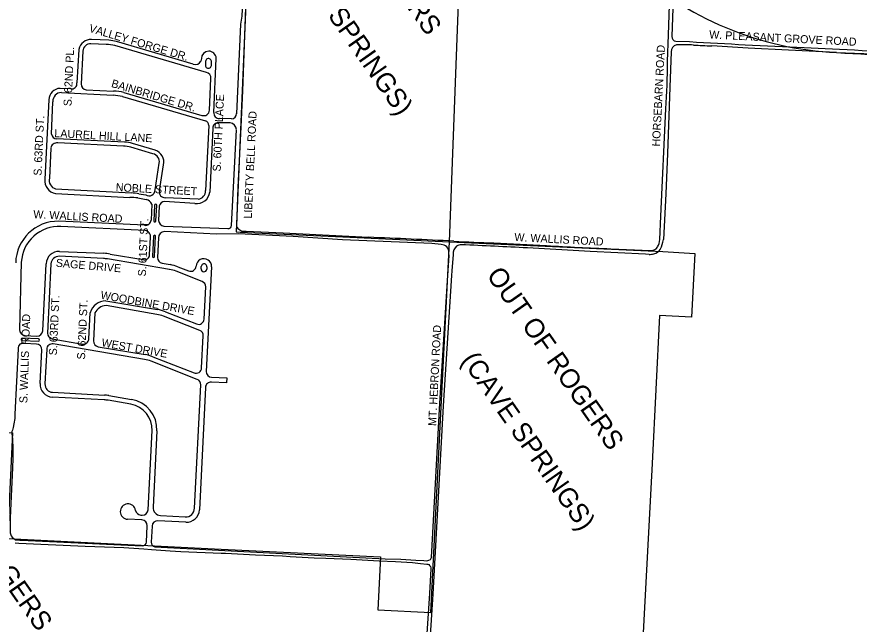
# Model space of a CAD drawing. Extents: x 0 to 712119, y 0 to 761125.
# Drawn here: x 662915 to 668176, y 714980 to 718772 of the extents above; entities that cross this region are included whole.
import ezdxf

# ---------------------------------------------------------------- set-up
doc = ezdxf.new("R2010")
doc.units = 0
for name, color, linetype in [('ISLANDS', 7, 'Continuous'), ('PAVED ROADS', 7, 'Continuous'), ('Priority 11', 7, 'Continuous'), ('street names', 7, 'Continuous')]:
    doc.layers.add(name, color=color, linetype=linetype)

msp = doc.modelspace()

# ---------------------------------------------------------------- linework, layer by layer
at = {"layer": 'ISLANDS'}
msp.add_lwpolyline([(664310.7, 717427.5), (664952, 717398.1), (665618, 717367.5), (665668.3, 718692.6), (665718.7, 720018.1), (664396.1, 720078.2), (664341, 718753), (664286, 717428.7)], close=True, dxfattribs=at)
msp.add_lwpolyline([(661495, 714923.1), (661558.5, 716237.1), (662888.7, 716173.6), (662856, 715514.6), (664191, 715448.9), (665185.7, 715399.9), (665169.4, 715068.9), (665500.5, 715052.6), (665517.3, 715383.6), (665517.3, 715383.6), (665550.9, 716046.6), (665618, 717367.5), (666949.9, 717306.3), (667149.6, 717295.4), (667129.4, 716895.9), (666929.7, 716906.8), (666883, 715983.1), (666813.6, 714653)], dxfattribs=at)
at = {"layer": 'PAVED ROADS'}
for points in [[(664348.9, 719553.2), (664330.1, 719144.4), (664334.3, 719088.5), (664319.5, 718776.1), (664312.8, 718725.5), (664287.5, 718167.6)], [(666979.9, 718493.1), (666985.1, 718659.1), (666999.1, 719096.3)], [(664346.9, 718946.4), (664323.7, 718310.1), (664314.2, 718086.4), (664296.1, 717706.8), (664287.6, 717465.3)], [(667016, 718946.1), (667006.1, 718650.1)], [(663489.8, 718625.9), (663381.7, 718630.8)], [(664016.6, 718476.6), (663537.4, 718617.4)], [(667032.1, 718620.5), (667117.3, 718617.5)], [(663302.4, 718569.1), (663290.7, 718359.9)], [(663327, 718558.4), (663316.7, 718353.8)], [(663473.2, 718600.4), (663378, 718604.4)], [(663473.2, 718600.4), (663473.2, 718600.4)], [(664098.9, 718424.8), (663527.7, 718593.1)], [(668035.7, 718549.2), (667734.6, 718563.3), (667484, 718576.1), (667255.1, 718590.4)], [(667465.1, 718598.3), (667743.8, 718585.4), (668053.1, 718570.2)], [(664067.8, 718511.5), (664064.8, 718495.9)], [(664144.8, 718175.9), (664160.4, 718512.5)], [(667002.6, 718553.5), (666994.6, 718332.4), (666979.7, 717918.7), (666967.7, 717666.3), (666953.6, 717382.1)], [(664094, 718493.6), (664093.1, 718469.7)], [(664130.2, 718469.4), (664131.1, 718490.6)], [(664117.6, 718188.7), (664127.5, 718386.9)], [(663251.4, 718322.4), (663186.1, 718325.6)], [(663193.2, 718298.8), (663517.6, 718282.7)], [(663348.9, 718317), (663519.8, 718309)], [(663583.9, 718300.3), (664071.1, 718157.1)], [(663115.1, 718253.5), (663090.4, 717757.8)], [(663131.5, 718039.2), (663140.5, 718242.5)], [(663575.2, 718274.5), (664093.5, 718123.3)], [(666930.4, 717382.6), (666937.3, 717527.6), (666968, 718198.8)], [(664256.2, 718134.4), (664180.3, 718137.4)], [(664113.3, 718094.7), (664094.2, 717687.1)], [(664247.5, 718109.7), (664174.2, 718111.4)], [(664139.3, 718076.1), (664120.2, 717678.4)], [(664254.9, 717469.2), (664286.4, 718067.7)], [(663587.2, 717989.7), (663164.2, 718011.4)], [(663580.4, 717964.7), (663170.4, 717984.7)], [(663779.2, 717940.3), (663636.8, 717982.1)], [(663126.8, 717953.2), (663118.5, 717764.9)], [(663765.5, 717917.3), (663627.2, 717958.6)], [(663779.5, 717691.1), (663804.7, 717858.5)], [(663806.2, 717685.8), (663830.9, 717847.1)], [(663156.5, 717668.5), (663620, 717644.7)], [(663157.5, 717697.6), (663630.5, 717672.7)], [(663677.3, 717667.9), (663721, 717660.3)], [(663670.2, 717641.8), (663723, 717630.8)], [(664027.5, 717607), (663837.7, 717618.2)], [(664047.2, 717633.8), (663842.4, 717643)], [(663757.7, 717602.9), (663753.8, 717503.4)], [(663774.8, 717595.3), (663769.9, 717499.4)], [(663783.8, 717498.7), (663788.8, 717594.5)], [(663804.7, 717589.9), (663800.7, 717499.9)], [(663712.3, 717470.4), (663176.4, 717496.2)], [(663716.9, 717437.2), (663190.3, 717462.5)], [(663832.3, 717465.9), (664234, 717451.2)], [(663768, 717401.6), (663761.8, 717277.4)], [(663768, 717401.6), (663768, 717401.6)], [(663775.8, 717276.7), (663782, 717400.9)], [(665507.8, 717356), (664949.4, 717380.4), (664641.8, 717400.8), (664298.3, 717416.3), (664162.5, 717414.5), (663836.8, 717431)], [(664336.1, 717433.9), (664347.4, 717433.9), (664577.9, 717423.6), (665111.9, 717395.5)], [(663743.9, 717287.7), (663749.7, 717395.1)], [(663799.6, 717392.4), (663793.5, 717269.7)], [(665893.9, 717360.5), (666223, 717343.7)], [(663181.9, 717306.8), (663457.9, 717295.6)], [(666863.8, 717289.1), (666842.6, 717290.2), (666495.8, 717306.5), (666104.3, 717328.9)], [(666624.6, 717324.2), (666870.6, 717312.5)], [(663457.4, 717263), (663180.4, 717276.8)], [(663457.4, 717263), (663457.4, 717263)], [(663867.6, 717195.4), (663481.8, 717260.3)], [(663497.4, 717290), (663703.7, 717256.3)], [(663775.8, 717276.7), (663775.8, 717276.7)], [(665216.5, 715387.6), (665313.6, 715386.3), (665407.3, 715379.9), (665457.6, 715376.7), (665475.4, 715375.7), (665489.1, 715379.1), (665498, 715384.3), (665502.9, 715392.1), (665505, 715396), (665558, 716360), (665606.9, 717156.3), (665609.3, 717188.1), (665614.7, 717282.6)], [(665639.7, 717287.7), (665632.1, 717187.1), (665630.1, 717156.3), (665577.7, 716344.1), (665513.8, 715166.3), (665497.6, 714909.4), (665488.4, 714777.2), (665477, 714642.8), (665467.3, 714536.9), (665459, 714421.3), (665443.7, 714234.9), (665439.6, 714144.1), (665441.3, 714079.1), (665442.9, 714012.9), (665443.8, 713890.4), (665441.1, 713784.1), (665434.9, 713591.6), (665431.9, 713498.7), (665428.2, 713427.2), (665434.2, 713414.3)], [(662943, 717240.1), (662932.6, 716819.6)], [(663077.2, 716812.4), (663098, 717230.8)], [(663128, 717229.3), (663106.4, 716797.1)], [(663822.6, 717233.4), (663872.6, 717225)], [(663920.5, 717211.7), (663987.3, 717185.5)], [(664066, 717199.1), (664066.7, 717212.8)], [(664130.9, 717211), (664098.4, 716558.5)], [(664102.7, 717210.9), (664102, 717197.2)], [(664072.5, 717119.7), (663909.6, 717183.8)], [(664084.7, 716885.2), (664094.6, 717085.4)], [(663470.6, 716998.5), (663794.6, 716944.1)], [(663789.6, 716914.5), (663472.5, 716968.7)], [(663842.6, 716930.7), (664036.9, 716854.4)], [(663365, 716761.9), (663373.1, 716924.4)], [(663403.1, 716922.9), (663394.4, 716748.7)], [(664057.3, 716814.1), (663831.6, 716902.8)], [(662965.8, 716782.9), (663040.5, 716779.2)], [(664069.4, 716579.6), (664079.4, 716779.8)], [(662941.7, 716759.5), (662941.6, 716758.5)], [(662947.8, 716751.7), (663049.4, 716746.7)], [(663050.1, 716760.7), (662948.5, 716765.7)], [(663038, 716729.2), (662964.6, 716732.9)], [(663056.2, 716752.8), (663056.2, 716753.8)], [(663135.6, 716760.9), (663324.2, 716729.1)], [(663711.7, 716633.5), (663142.2, 716729.3)], [(662922.6, 716699.4), (662903, 716290.5), (662901.7, 716264.8), (662897.2, 716230.5), (662891.3, 716207.5), (662888.1, 716190.8), (662884.5, 716183.2), (662884.5, 716169.7), (662887.2, 716134.9), (662889, 716116.9), (662890.8, 716094.8), (662890.7, 716014.8), (662888.5, 715956.5), (662873.9, 715643.5), (662872.6, 715575.4), (662873.9, 715549.5), (662880.1, 715531.2), (662886.8, 715522.2), (662906.1, 715507.1), (662933.3, 715503.5), (662943, 715503.5), (663698.8, 715469)], [(663060.7, 716481.6), (663071.2, 716692.5)], [(663101.4, 716696.6), (663090.6, 716480.1)], [(663423.5, 716712.4), (663716.6, 716663.1)], [(664042, 716508.5), (663753.7, 716621.9)], [(663764.6, 716649.8), (664021.7, 716548.7)], [(664131.6, 716521.8), (664226.5, 716517.1), (664225, 716487.1), (664130.1, 716491.8)], [(664024.8, 715704), (664064.2, 716474.2)], [(664093.4, 716458.6), (664055.3, 715692.8)], [(663137.9, 716427.7), (663462.6, 716410.2)], [(663489.5, 716407.2), (663631.3, 716383.4)], [(663461, 716380.3), (663136.3, 716397.7)], [(663626.3, 716353.8), (663484.5, 716377.7)], [(663734.9, 715693.7), (663759.6, 716188.1)], [(663789.5, 716186.6), (663766.9, 715709.9)], [(663789.5, 716186.6), (663789.5, 716186.6)], [(663696.7, 715630.6), (663607, 715635)], [(663689.6, 715660.9), (663698.2, 715660.5)], [(663971.4, 715616.9), (663796.6, 715625.6)], [(663811.7, 715657.7), (663967.2, 715649.7)], [(663724.9, 715492.8), (663730, 715593.9)], [(663759.9, 715592.4), (663754.9, 715491.3), (663754.9, 715491.3)], [(662904.8, 715487.7), (662927.6, 715486.2), (663342.7, 715465.8), (663583.5, 715458.6), (663708.1, 715449.3), (663756.3, 715446.2), (663873, 715438.5), (663940.1, 715434.3), (664191.8, 715423.2), (664218.9, 715423.6), (664406.6, 715413.7), (664573.7, 715405.7), (664622.5, 715402), (664696.5, 715399), (664771.5, 715394), (664845.5, 715391), (665001, 715385), (665178.5, 715376), (665280, 715371), (665386.5, 715364.5), (665436.5, 715359), (665476.5, 715354.5), (665483, 715353.5), (665488.5, 715351.5), (665493, 715347), (665498, 715340), (665501, 715332.5), (665501, 715324.5), (665492.6, 715172), (665480, 714983.6), (665466.1, 714767.4)], [(663777.6, 715463.4), (664572.7, 715421.4), (665216.5, 715387.6)]]:
    msp.add_lwpolyline(points, dxfattribs=at)
msp.add_lwpolyline([(664310.4, 718727.8), (664310.4, 718727.8), (664310.4, 718727.8), (664310.4, 718727.8), (664310.4, 718727.8)], close=True, dxfattribs=at)
for centre, radius, start, end in [((663378.6, 718552.9), 78, 87.7687, 168.0083), ((663478.3, 718423.2), 203, 73.0725, 86.7674), ((667034.2, 718648.6), 28.2, 176.9204, 265.8031), ((669070.9, 750887.8), 32329.4, 266.53573, 267.15305), ((663377, 718554.1), 50.3, 88.8752, 175.0808), ((663461.7, 718308.6), 292, 76.9346, 87.7527), ((664114.1, 718511.5), 46.3, 1.2247, 180.1138), ((667045.1, 718555.2), 42.5, 103.9054, 182.2865), ((667082.2, 717694.2), 903.6, 86.2496, 93.0001), ((668040.7, 736476), 17902.8, 267.12026, 267.48483), ((673192.1, 815630), 97195.7, 266.969225, 267.41493), ((664112.7, 718493.2), 18.6, 352.0387, 178.8148), ((664170.4, 718512), 10, 177.0447, 177.0452), ((671419.7, 781551.1), 63092.8, 266.925456, 267.292135), ((664030.8, 718510.9), 37.1, 247.4444, 336.2536), ((664111.6, 718469.4), 18.5, 179.2582, 359.9103), ((662054.3, 718544.6), 4925.9, 355.9747, 359.4009), ((664091.8, 718389.8), 35.8, 355.5002, 78.6309), ((663256.7, 718356.3), 34.2, 261.1814, 5.9996), ((663352.7, 718352.7), 36, 178.3182, 263.921), ((663187.8, 718252.8), 72.8, 91.3587, 179.4564), ((663191.7, 718247.4), 51.4, 88.2835, 185.5466), ((663507.7, 717979.1), 330.1, 76.6548, 87.9001), ((663503.6, 717975.6), 307.4, 76.525, 87.3759), ((664083, 718189.5), 34.5, 249.7218, 358.6098), ((664179.9, 718172.6), 35.2, 174.6804, 270.6987), ((664253.2, 718168.6), 34.3, 275.0079, 358.3682), ((664084.6, 718096), 28.7, 357.4762, 72.0976), ((664172.4, 718078.2), 33.2, 86.904, 183.6577), ((664244.5, 718067.9), 41.9, 359.815, 85.8333), ((663164.9, 718045.3), 34, 190.4215, 268.7361), ((663164, 717947.7), 37.6, 80.1103, 171.5252), ((663580.6, 717780.9), 208.9, 74.397, 88.179), ((663582.1, 717796.5), 168.3, 74.4229, 90.5652), ((663753.7, 717865.2), 79.3, 346.8098, 71.265), ((663753.1, 717866.6), 52.2, 351.0431, 76.3108), ((663171.7, 717748.9), 81.8, 173.7648, 259.2622), ((663173, 717751.5), 56.1, 166.1671, 253.9545), ((663605.5, 717197.9), 475.5, 81.3082, 86.9849), ((663741.4, 717692.4), 38.1, 237.5244, 358.069), ((663839.6, 717677.4), 34.5, 165.7821, 274.7152), ((664039.2, 717687.8), 81.6, 261.7576, 353.3974), ((664041.6, 717686.2), 52.6, 276.177, 1.001), ((663570.9, 716364.6), 1281, 85.5533, 87.8035), ((663719.4, 717590.8), 40.1, 17.5808, 84.8633), ((663837.9, 717584.6), 33.6, 90.2939, 170.884), ((663781.8, 717594.9), 7, 357.0451, 177.0451), ((663173.7, 717230.2), 266, 89.4116, 178.7163), ((663177.1, 717228.5), 234.4, 86.7864, 177.1706), ((663718.3, 717505.4), 35.6, 260.3321, 356.7444), ((663776.9, 717499), 7, 177.0452, 357.0469), ((663835.4, 717500.5), 34.7, 180.8906, 264.7587), ((664239.2, 717466.2), 15.9, 250.7446, 10.7791), ((664320.5, 717473.5), 33.9, 194.0491, 247.9144), ((663713.3, 717400.6), 36.8, 351.4395, 84.344), ((663775, 717401.2), 7, 357.1454, 177.1504), ((663840.3, 717390.4), 40.8, 94.9639, 177.1808), ((664329, 717462.3), 29.3, 223.5293, 284.0258), ((662583.5, 655225.7), 62221.3, 87.180151, 87.671174), ((665481.7, 716801.2), 555.4, 79.4629, 87.3094), ((666170.6, 726368.6), 9012.4, 266.65347, 268.24026), ((665688.1, 717306), 43.1, 84.3274, 127.3908), ((664017.7, 678579.6), 38805.4, 86.9176, 87.52655), ((666847.7, 717381.7), 82.7, 325.6275, 0.6179), ((666779.6, 717403.8), 175.4, 331.5989, 352.875), ((663177.9, 717226.9), 80, 87.1479, 177.1479), ((663447.8, 717081.4), 214.4, 76.6081, 87.3009), ((665564.6, 717300.5), 50.3, 20.6124, 68.2062), ((665126, 717259.1), 489.2, 2.7524, 6.9397), ((665705.6, 717290.8), 66, 131.461, 182.6842), ((667203, 733340.7), 16026.9, 266.49441, 267.93182), ((666876.8, 717356.9), 44.9, 262.0681, 330.7807), ((666883.3, 717349.9), 58.5, 280.0288, 329.7331), ((663177.9, 717226.9), 50, 87.1479, 177.1479), ((663447, 717053.3), 210, 80.448, 87.1479), ((663711.9, 717287.2), 32, 255.0219, 0.9167), ((663768.8, 717277), 7, 177.1479, 357.1479), ((663775.8, 717276.7), 0.000000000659, 45, 135), ((663828.4, 717267.9), 35, 177.1479, 260.448), ((664083, 717213.5), 48, 357.0446, 177.0451), ((666870.8, 717364.5), 75.7, 264.6839, 287.4347), ((663832.7, 716988.3), 210, 68.5387, 80.448), ((663832.7, 716988.3), 240, 68.5387, 80.448), ((664000.1, 717218), 35, 248.5404, 356.602), ((664084, 717198.2), 18, 177.0463, 356.8888), ((664084.7, 717211.8), 18, 357.0446, 177.0451), ((664059.7, 717087.2), 35, 357.1479, 68.5387), ((663471.5, 716896.1), 102.4, 90.5056, 163.9539), ((663475.1, 716889.3), 79.5, 91.8922, 154.9766), ((663754.8, 716707.4), 240, 68.5387, 80.448), ((663754.8, 716707.4), 210, 68.5387, 80.448), ((664049.7, 716886.9), 35, 248.5387, 357.1479), ((662967.6, 716817.8), 35, 177.1985, 267.129), ((663042.2, 716814.1), 35, 267.1479, 357.1479), ((663141.4, 716795.4), 35, 177.1479, 260.448), ((664044.4, 716781.5), 35, 357.1479, 68.5387), ((662955.1, 716701.7), 32.6, 73.1215, 183.9092), ((662948.1, 716758.2), 6.5, 177.1479, 267.1479), ((662948.2, 716759.2), 6.5, 87.1479, 177.1479), ((663036.2, 716694.3), 35, 357.1479, 87.1479), ((663049.7, 716753.2), 6.5, 267.1479, 357.1479), ((663049.7, 716754.2), 6.5, 357.1479, 87.1479), ((663136.4, 716694.8), 35, 80.448, 177.1479), ((663330, 716763.6), 35, 260.448, 357.1479), ((663429.3, 716746.9), 35, 177.1479, 260.448), ((663676.8, 716426.4), 210, 68.5387, 80.448), ((663676.8, 716426.4), 240, 68.5387, 80.448), ((664034.5, 716581.3), 35, 248.5387, 357.1479), ((664029.2, 716475.9), 35, 357.1479, 68.5387), ((664133.4, 716556.8), 35, 177.1481, 267.1481), ((663140.6, 716477.6), 80, 177.1479, 266.9233), ((663140.6, 716477.6), 50, 177.1479, 266.9233), ((664128.4, 716456.9), 35, 87.1479, 177.1481), ((663449.7, 716170.6), 240, 80.448, 86.9233), ((663449.7, 716170.6), 210, 80.448, 86.9233), ((663599.8, 716196), 160, 357.1479, 80.448), ((663599.8, 716196), 190, 357.1479, 80.448), ((663609.4, 715683), 48, 8.9668, 267.1479), ((663691.4, 715695.9), 35, 188.9668, 267.1479), ((663700, 715695.5), 35, 267.1479, 357.1479), ((663815.9, 715706.6), 49.1, 176.1311, 265.042), ((663970.5, 715703.9), 54.3, 266.5665, 0.0833), ((663975.4, 715696.8), 80, 267.1479, 357.1479), ((663695, 715595.6), 35, 357.1479, 87.1479), ((663794.9, 715590.6), 35, 87.1479, 177.1479), ((663700, 715494), 25, 267.3913, 357.1479), ((663783.5, 715491.4), 28.6, 180.0873, 258.2086)]:
    msp.add_arc(centre, radius, start, end, dxfattribs=at)
at = {"layer": 'Priority 11'}
msp.add_lwpolyline([(668035.7, 718549.2), (669564.9, 718492.9), (670028.3, 718562.8), (670397.3, 718550), (670799.9, 718421.5), (671357.4, 718377.7), (671357.4, 718377.7), (671803.7, 718259.9), (672268.1, 718018.9)], dxfattribs=at)
msp.add_arc((668129.8, 720581.9), 2034.9, 227.173, 267.3497, dxfattribs=at)

# ---------------------------------------------------------------- texts
at = {"layer": 'ISLANDS'}
for s, p in [('OUT OF ROGERS', (664705.7, 719750.4)), ('(CAVE SPRINGS)', (664547.3, 719219.5)), ('OUT OF ROGERS', (665845.1, 717158.3)), ('(CAVE SPRINGS)', (665686.7, 716627.3)), ('OUT OF ROGERS', (662275.1, 716029.7))]:
    msp.add_text(s, height=120, rotation=305, dxfattribs=at).set_placement(p)
at = {"layer": 'street names'}
for s, rotation, p in [('VALLEY FORGE DR.', 343.4102, (663361.9, 718680)), ('W. PLEASANT GROVE ROAD', 357.1138, (667238.5, 718637.7)), ('S. 62ND PL.', 87.3557, (663256.1, 718213.4)), ('HORSEBARN ROAD', 87.1461, (666931.8, 717961.5)), ('BAINBRIDGE DR.', 343.4102, (663501.1, 718335.6)), ('S. 60TH PLACE', 87.3557, (664187.9, 717805.5)), ('S. 63RD ST.', 87.3557, (663069, 717779.2)), ('LIBERTY BELL ROAD', 87.3557, (664382.4, 717511.3)), ('LAUREL HILL LANE', 356.9838, (663148.3, 718021.2)), ('NOBLE STREET', 356.9838, (663531.9, 717684.2)), ('W. WALLIS ROAD', 356.9838, (663016.9, 717515.3)), ('S. 61ST ST.', 87.3557, (663720.6, 717150.6)), ('W. WALLIS ROAD', 356.9838, (666021.7, 717372.6)), ('SAGE DRIVE', 355, (663157.1, 717212.2)), ('WOODBINE DRIVE', 349.9838, (663435.3, 717012.6)), ('S. 63RD ST.', 87.3557, (663164.5, 716657.7)), ('S. 62ND ST.', 87.3557, (663340.5, 716631.2)), ('S. WALLIS  ROAD', 88.0489, (662980.4, 716359.1)), ('MT. HEBRON ROAD', 87.1138, (665533.8, 716216.2)), ('WEST DRIVE', 349.9838, (663441.3, 716715.1))]:
    msp.add_text(s, height=50, rotation=rotation, dxfattribs=at).set_placement(p)

doc.saveas('drawing.dxf')
